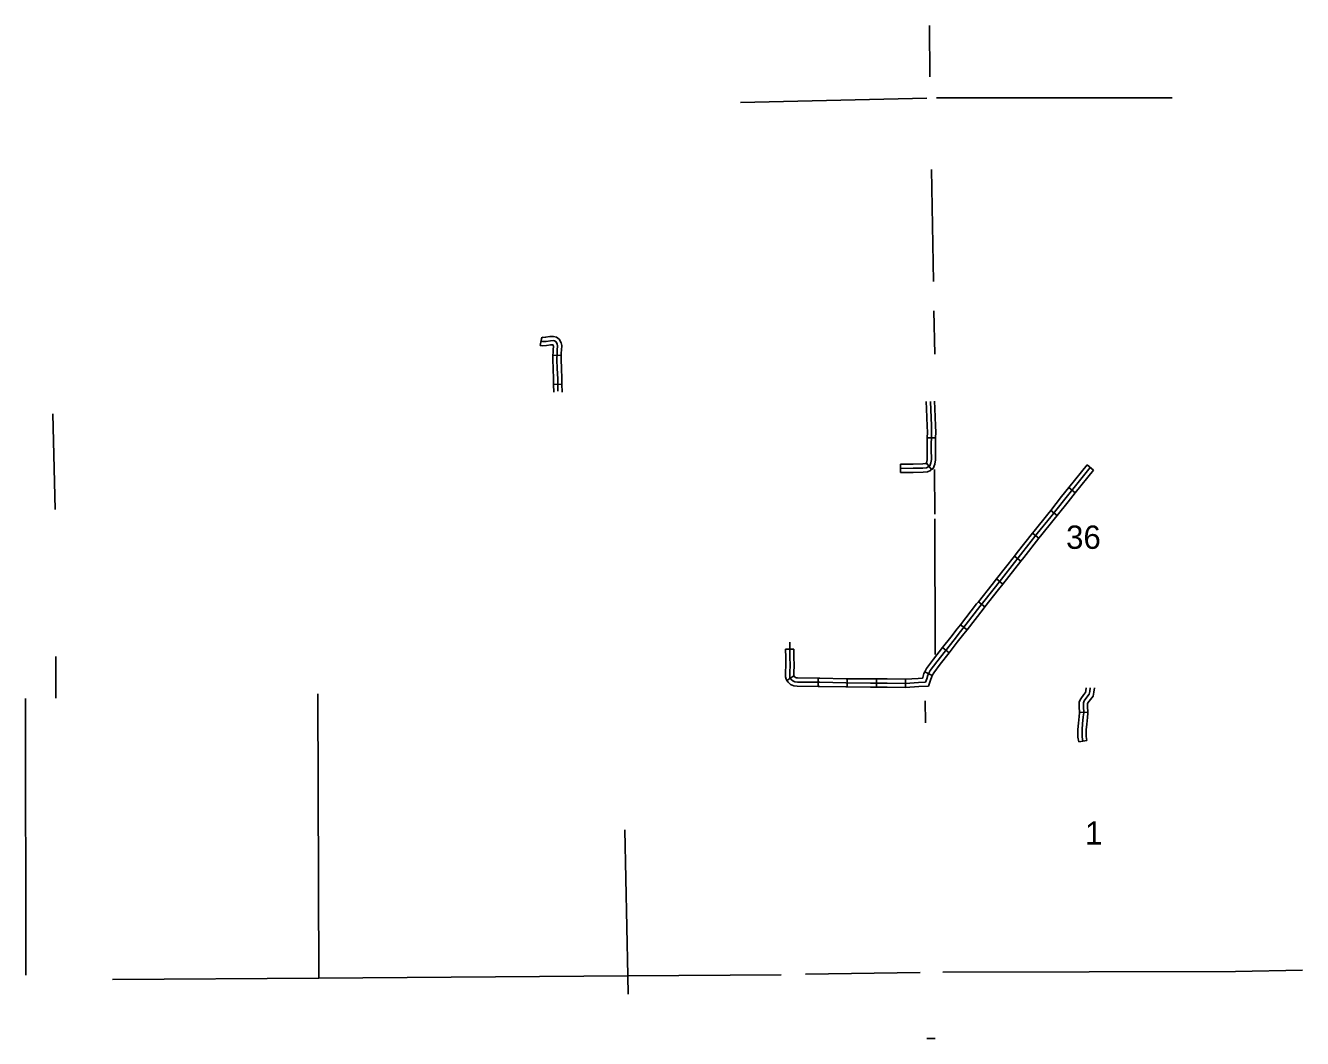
# Model space of a CAD drawing. Extents: x 1127717 to 1741049, y 2026793 to 2244711.
# Drawn here: x 1507799 to 1530945, y 2178159 to 2196528 of the extents above; entities that cross this region are included whole.
import ezdxf

# ---------------------------------------------------------------- set-up
doc = ezdxf.new("R2010")
doc.units = 0
doc.layers.add('32', color=7, linetype='Continuous')
doc.layers.add('5', color=7, linetype='Continuous')

msp = doc.modelspace()

# ---------------------------------------------------------------- linework, layer by layer
at = {"layer": '32'}
for p, q in [((1517130, 2190728), (1517155, 2190876)), ((1517359, 2190552), (1517509, 2190547)), ((1517372, 2190020), (1517522, 2190023)), ((1524295, 2189050), (1524145, 2189052)), ((1523656, 2188423), (1523656, 2188573)), ((1524223, 2188475), (1524130, 2188593)), ((1527040, 2188561), (1527157, 2188467)), ((1526710, 2188148), (1526827, 2188055)), ((1526381, 2187735), (1526498, 2187642)), ((1526050, 2187323), (1526168, 2187230)), ((1525724, 2186908), (1525842, 2186815)), ((1525398, 2186492), (1525516, 2186400)), ((1525071, 2186078), (1525189, 2185985)), ((1524746, 2185661), (1524865, 2185569)), ((1521725, 2185219), (1521575, 2185217)), ((1524420, 2185246), (1524539, 2185154)), ((1524101, 2184809), (1524234, 2184740)), ((1521725, 2184735), (1521601, 2184652)), ((1522165, 2184694), (1522164, 2184544)), ((1522693, 2184683), (1522692, 2184533)), ((1523221, 2184680), (1523221, 2184530)), ((1523750, 2184674), (1523747, 2184524)), ((1527054, 2184078), (1526904, 2184071)), ((1527039, 2183562), (1526892, 2183536)), ((1524288, 2178159), (1524138, 2178159))]:
    msp.add_line(p, q, dxfattribs=at)
for points in [[(1517142, 2190802), (1517170, 2190797), (1517234, 2190800), (1517312, 2190813), (1517360, 2190816), (1517390, 2190809), (1517415, 2190790), (1517436, 2190749), (1517442, 2190719), (1517438, 2190644), (1517436, 2190593), (1517431, 2190465), (1517438, 2190311), (1517445, 2190119), (1517449, 2189898)], [(1517155, 2190876), (1517175, 2190873), (1517226, 2190874), (1517303, 2190888), (1517367, 2190891), (1517421, 2190878), (1517474, 2190840), (1517507, 2190775), (1517518, 2190726), (1517513, 2190640), (1517510, 2190590), (1517509, 2190547)], [(1517130, 2190728), (1517165, 2190722), (1517242, 2190725), (1517320, 2190739), (1517353, 2190740), (1517357, 2190739), (1517364, 2190724), (1517367, 2190713), (1517363, 2190648), (1517361, 2190596), (1517359, 2190552)], [(1517359, 2190552), (1517356, 2190465), (1517363, 2190308), (1517370, 2190117), (1517372, 2190020)], [(1517509, 2190547), (1517506, 2190465), (1517513, 2190314), (1517520, 2190121), (1517522, 2190023)], [(1517372, 2190020), (1517374, 2189880)], [(1517522, 2190023), (1517524, 2189882)], [(1523656, 2188498), (1523664, 2188498), (1523889, 2188500), (1524066, 2188503), (1524130, 2188509), (1524163, 2188524), (1524189, 2188544), (1524211, 2188595), (1524220, 2188656), (1524216, 2188843), (1524222, 2189155), (1524218, 2189267), (1524202, 2189712)], [(1524132, 2189576), (1524127, 2189709)], [(1524282, 2189581), (1524277, 2189714)], [(1524145, 2189052), (1524147, 2189155), (1524143, 2189265), (1524132, 2189576)], [(1524295, 2189050), (1524297, 2189156), (1524293, 2189270), (1524282, 2189581)], [(1524127, 2188591), (1524138, 2188616), (1524145, 2188661), (1524141, 2188843), (1524145, 2189052)], [(1524223, 2188475), (1524250, 2188497), (1524283, 2188574), (1524295, 2188651), (1524291, 2188843), (1524295, 2189050)], [(1523656, 2188573), (1523663, 2188573), (1523888, 2188575), (1524062, 2188578), (1524111, 2188583), (1524124, 2188588), (1524130, 2188593)], [(1523656, 2188423), (1523664, 2188423), (1523890, 2188425), (1524070, 2188428), (1524149, 2188435), (1524202, 2188459), (1524223, 2188475)], [(1527098, 2188514), (1526639, 2187939), (1526386, 2187621), (1526138, 2187314), (1525834, 2186927), (1525379, 2186347), (1525098, 2185991), (1524748, 2185542), (1524629, 2185391)], [(1527040, 2188561), (1526710, 2188148)], [(1527157, 2188467), (1526827, 2188055)], [(1526710, 2188148), (1526580, 2187986), (1526381, 2187735)], [(1526827, 2188055), (1526697, 2187892), (1526498, 2187642)], [(1526381, 2187735), (1526327, 2187668), (1526080, 2187360), (1526050, 2187323)], [(1526498, 2187642), (1526444, 2187574), (1526197, 2187267), (1526168, 2187230)], [(1526050, 2187323), (1525775, 2186973), (1525724, 2186908)], [(1526168, 2187230), (1525893, 2186880), (1525842, 2186815)], [(1525724, 2186908), (1525398, 2186492)], [(1525842, 2186815), (1525516, 2186400)], [(1525398, 2186492), (1525320, 2186393), (1525071, 2186078)], [(1525516, 2186400), (1525438, 2186300), (1525189, 2185985)], [(1525071, 2186078), (1525039, 2186038), (1524746, 2185661)], [(1525189, 2185985), (1525157, 2185945), (1524865, 2185569)], [(1524746, 2185661), (1524689, 2185588), (1524570, 2185438), (1524420, 2185246)], [(1524865, 2185569), (1524807, 2185496), (1524688, 2185345), (1524539, 2185154)], [(1521601, 2184652), (1521586, 2184674), (1521575, 2184718), (1521575, 2184795), (1521583, 2184930), (1521578, 2185069), (1521575, 2185217)], [(1524111, 2184621), (1523986, 2184613), (1523750, 2184599), (1523418, 2184605), (1523117, 2184605), (1522670, 2184608), (1522196, 2184619), (1521789, 2184622), (1521746, 2184628), (1521707, 2184645), (1521678, 2184670), (1521655, 2184704), (1521650, 2184727), (1521650, 2184793), (1521658, 2184929), (1521653, 2185071), (1521650, 2185267), (1521653, 2185347)], [(1521725, 2184735), (1521725, 2184735), (1521725, 2184736), (1521725, 2184790), (1521733, 2184928), (1521728, 2185073), (1521725, 2185219)], [(1524420, 2185246), (1524257, 2185036), (1524133, 2184871), (1524101, 2184809)], [(1524629, 2185391), (1524316, 2184990), (1524197, 2184831), (1524154, 2184748), (1524134, 2184680), (1524111, 2184621)], [(1524539, 2185154), (1524376, 2184945), (1524261, 2184791), (1524234, 2184740)], [(1524101, 2184809), (1524084, 2184776), (1524063, 2184704), (1524059, 2184693), (1523982, 2184688), (1523749, 2184674), (1523750, 2184674)], [(1522164, 2184544), (1521784, 2184547), (1521726, 2184555), (1521666, 2184581), (1521621, 2184621), (1521601, 2184652)], [(1522165, 2184694), (1521794, 2184697), (1521767, 2184701), (1521748, 2184709), (1521735, 2184720), (1521725, 2184735)], [(1522692, 2184533), (1522669, 2184533), (1522194, 2184544), (1522164, 2184544)], [(1522693, 2184683), (1522671, 2184683), (1522197, 2184694), (1522165, 2184694)], [(1523221, 2184530), (1523116, 2184530), (1522692, 2184533)], [(1523221, 2184680), (1523117, 2184680), (1522693, 2184683)], [(1523750, 2184674), (1523419, 2184680), (1523221, 2184680)], [(1523747, 2184524), (1523417, 2184530), (1523221, 2184530)], [(1524234, 2184740), (1524224, 2184721), (1524205, 2184656), (1524164, 2184548), (1523991, 2184539), (1523752, 2184524), (1523747, 2184524)], [(1526904, 2184071), (1526899, 2184175), (1526899, 2184262), (1526926, 2184320), (1526979, 2184395), (1527010, 2184435), (1527017, 2184466), (1527024, 2184518)], [(1527054, 2184078), (1527049, 2184179), (1527049, 2184229), (1527056, 2184245), (1527100, 2184306), (1527149, 2184369), (1527164, 2184440), (1527175, 2184519)], [(1526966, 2183549), (1526951, 2183631), (1526951, 2183759), (1526960, 2183867), (1526971, 2183990), (1526980, 2184064), (1526974, 2184177), (1526974, 2184246), (1526991, 2184283), (1527039, 2184351), (1527079, 2184402), (1527091, 2184453), (1527099, 2184516)], [(1526892, 2183536), (1526876, 2183625), (1526876, 2183762), (1526885, 2183874), (1526897, 2183997), (1526905, 2184066), (1526904, 2184071)], [(1527039, 2183562), (1527026, 2183638), (1527026, 2183756), (1527035, 2183861), (1527046, 2183982), (1527055, 2184061), (1527054, 2184078)]]:
    msp.add_lwpolyline(points, dxfattribs=at)
at = {"layer": '5'}
for points in [[(1524185, 2196528), (1524192, 2195597)], [(1520758, 2195131), (1524138, 2195212)], [(1524310, 2195214), (1528583, 2195215)], [(1524219, 2193916), (1524256, 2191889)], [(1524266, 2191357), (1524280, 2190570)], [(1508296, 2189487), (1508336, 2187752)], [(1524277, 2188479), (1524280, 2187664)], [(1524280, 2187583), (1524290, 2185123)], [(1508348, 2185086), (1508346, 2184332)], [(1507799, 2184324), (1507806, 2179307)], [(1513098, 2184407), (1513116, 2179255)], [(1524103, 2184281), (1524110, 2183881)], [(1518659, 2181941), (1518718, 2179293)], [(1509375, 2179227), (1513116, 2179255)], [(1513116, 2179255), (1518718, 2179293)], [(1518718, 2179293), (1521493, 2179314)], [(1518718, 2179293), (1518724, 2178965)], [(1521937, 2179322), (1524014, 2179357)], [(1524424, 2179360), (1529729, 2179372)], [(1529729, 2179372), (1530945, 2179395)]]:
    msp.add_lwpolyline(points, dxfattribs=at)

# ---------------------------------------------------------------- texts
for s, height, p in [('36', 422.4, (1526661, 2187038)), ('1', 422, (1527004, 2181673))]:
    msp.add_text(s, height=height, dxfattribs=at).set_placement(p)

doc.saveas('drawing.dxf')
